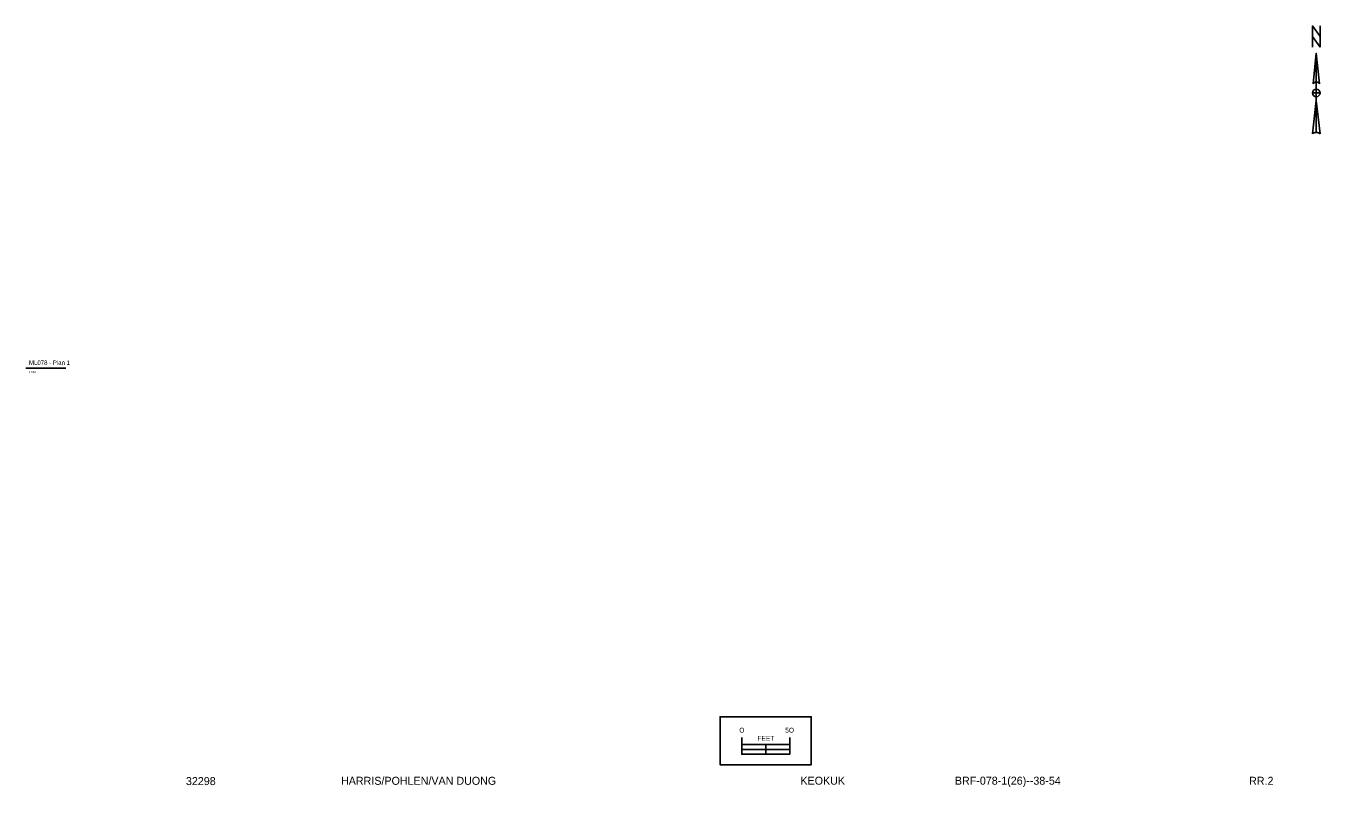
# Model space of a CAD drawing. Extents: x -0.12 to 2.57, y 0.07 to 1.66.
import ezdxf

# ---------------------------------------------------------------- set-up
doc = ezdxf.new("R2010")
doc.units = 0
doc.layers.add('Cell', color=7, linetype='Continuous')
doc.layers.add('SheetText', color=7, linetype='Continuous')

msp = doc.modelspace()

# ---------------------------------------------------------------- linework, layer by layer
at = {"layer": 'Cell'}
for p, q in [((2.5636, 1.6013), (2.5699, 1.5379)), ((2.5636, 1.6013), (2.5636, 1.4365)), ((2.5573, 1.5379), (2.5573, 1.5379)), ((2.5575, 1.5385), (2.5587, 1.5398)), ((2.5636, 1.511), (2.5636, 1.511)), ((2.5557, 1.4334), (2.5636, 1.5031))]:
    msp.add_line(p, q, dxfattribs=at)
msp.add_lwpolyline([(2.5715, 1.614), (2.5557, 1.6362), (2.5557, 1.6584), (2.5715, 1.6362)], close=True, dxfattribs=at)
for points in [[(2.5557, 1.614), (2.5557, 1.6584), (2.5715, 1.6362), (2.5715, 1.6584)], [(2.5573, 1.5379), (2.5636, 1.6013), (2.5636, 1.5411)], [(2.5636, 1.511), (2.5636, 1.5189), (2.5557, 1.5189)], [(2.5715, 1.5189), (2.5636, 1.5189), (2.5636, 1.5268)], [(2.5636, 1.4365), (2.5636, 1.5031), (2.5715, 1.4334)]]:
    msp.add_lwpolyline(points, dxfattribs=at)
for centre, radius, start, end in [((2.5636, 1.5332), 0.00792, 90.0204, 143.1257), ((2.5636, 1.5332), 0.00792, 36.8481, 90.0218), ((2.5636, 1.5189), 0.00792, 90, 180), ((2.5636, 1.5189), 0.00792, 180, 270), ((2.5636, 1.5189), 0.00792, 0, 90), ((2.5636, 1.5189), 0.00792, 270, 360), ((2.5636, 1.425), 0.0115, 89.9894, 133.619), ((2.5636, 1.425), 0.0115, 46.4021, 90.0006)]:
    msp.add_arc(centre, radius, start, end, dxfattribs=at)
at = {"layer": 'SheetText'}
for p, q in [((-0.1242, 0.946), (-0.0413, 0.946)), ((1.4167, 0.142), (1.4167, 0.162)), ((1.4167, 0.142), (1.4167, 0.162))]:
    msp.add_line(p, q, dxfattribs=at)
for points in [[(1.3217, 0.22), (1.5117, 0.22), (1.5117, 0.12), (1.3217, 0.12)], [(1.3217, 0.22), (1.5117, 0.22), (1.5117, 0.12), (1.3217, 0.12)], [(1.3217, 0.12), (1.3217, 0.22), (1.5117, 0.22), (1.5117, 0.12)], [(1.4167, 0.1521), (1.4667, 0.1521), (1.4667, 0.162), (1.4167, 0.162)], [(1.3667, 0.142), (1.4167, 0.142), (1.4167, 0.1521), (1.3667, 0.1521)]]:
    msp.add_lwpolyline(points, close=True, dxfattribs=at)
for points in [[(1.3667, 0.177), (1.3667, 0.142), (1.4667, 0.142), (1.4667, 0.177)], [(1.3667, 0.162), (1.4667, 0.162)]]:
    msp.add_lwpolyline(points, dxfattribs=at)

# ---------------------------------------------------------------- texts
for s, height, p in [('ML078 - Plan 1', 0.009115, (-0.1177, 0.9526)), ('1"=50\'', 0.00391, (-0.1177, 0.9356)), ('O', 0.01, (1.3617, 0.187)), ('5O', 0.01, (1.4573, 0.187)), ('FEET', 0.01, (1.3997, 0.17)), ('32298', 0.01667, (0.2092, 0.0777)), ('HARRIS/POHLEN/VAN DUONG', 0.016667, (0.5322, 0.0783)), ('KEOKUK', 0.01667, (1.4891, 0.0785)), ('BRF-078-1(26)--38-54', 0.016667, (1.8108, 0.0785)), ('RR.2', 0.01667, (2.4236, 0.0783))]:
    msp.add_text(s, height=height, dxfattribs=at).set_placement(p)

doc.saveas('drawing.dxf')
